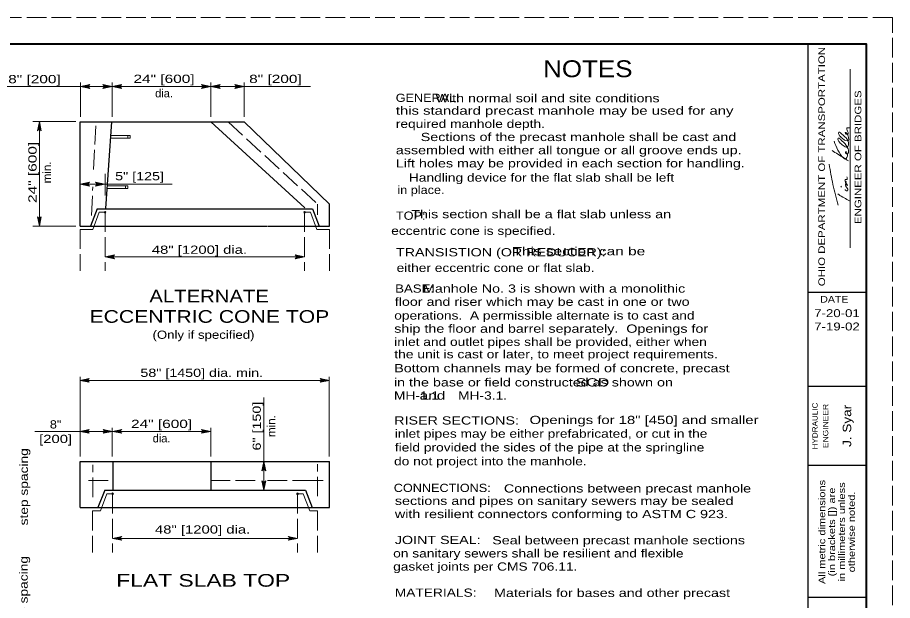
# Model space of a CAD drawing. Extents: x 808.4 to 842.4, y 1034.6 to 1056.6.
# Drawn here: x 825.84 to 842.44, y 1045.57 to 1056.63 of the extents above; entities that cross this region are included whole.
import ezdxf
from ezdxf.enums import TextEntityAlignment as Align

# ---------------------------------------------------------------- set-up
doc = ezdxf.new("R2010")
doc.units = 0
doc.header["$LTSCALE"] = 0.062
doc.header["$PDMODE"] = 32
doc.header["$PDSIZE"] = 0.031
doc.linetypes.add('LONG_DASHED', pattern=[7.5, 6, -1.5])
doc.layers.add('1', color=7, linetype='Continuous', lineweight=13)
doc.layers.add('10', color=7, linetype='Continuous')

msp = doc.modelspace()

# ---------------------------------------------------------------- linework, layer by layer
at = {"layer": '1', "lineweight": 25}
for p, q in [((840.83883, 1035.12767), (840.83883, 1056.12767)), ((827.02858, 1052.67158), (827.02858, 1054.6505)), ((827.02858, 1054.6505), (830.14142, 1054.6505)), ((827.51825, 1053.00408), (827.63133, 1054.64783)), ((831.29008, 1053.015), (829.51208, 1054.6505)), ((831.76025, 1053.08867), (830.14142, 1054.6505)), ((827.02858, 1052.67158), (827.02858, 1053.36142)), ((831.76025, 1052.67158), (831.76025, 1053.08867)), ((827.35492, 1053.00033), (827.22658, 1052.67158)), ((827.35492, 1053.00033), (827.22658, 1052.67158)), ((827.35492, 1053.00033), (831.27842, 1053.00033)), ((831.27842, 1053.00033), (831.43783, 1053.00033)), ((831.43783, 1053.00033), (831.56625, 1052.67158)), ((827.02858, 1052.67158), (830.57067, 1052.67158)), ((830.58167, 1052.67158), (831.27842, 1052.67158)), ((831.27842, 1052.67158), (831.76025, 1052.67158)), ((841.93883, 1051.41183), (840.83883, 1051.41183)), ((841.93883, 1049.62767), (840.83883, 1049.62767)), ((827.02858, 1048.20558), (831.27842, 1048.20558)), ((827.65292, 1048.20375), (827.65292, 1048.021)), ((829.51225, 1048.19792), (829.51225, 1048.021)), ((831.27842, 1048.20558), (831.76025, 1048.20558)), ((841.93883, 1048.12767), (840.83883, 1048.12767)), ((827.65292, 1048.021), (827.65292, 1047.66925)), ((829.51225, 1048.021), (829.51225, 1047.66342)), ((827.49775, 1047.66), (827.36933, 1047.33125)), ((827.49775, 1047.66), (827.36933, 1047.33125)), ((827.49775, 1047.66), (831.30233, 1047.66)), ((831.30233, 1047.66), (831.43075, 1047.33125)), ((831.30233, 1047.66), (831.43075, 1047.33125)), ((827.02858, 1047.33125), (830.58167, 1047.33125)), ((830.58167, 1047.33125), (831.76025, 1047.33125)), ((841.93883, 1045.62767), (840.83883, 1045.62767))]:
    msp.add_line(p, q, dxfattribs=at)
at = {"layer": '1'}
for p, q in [((841.63758, 1052.25867), (841.63758, 1055.64875)), ((827.19817, 1055.341), (827.03792, 1055.31858)), ((827.19275, 1055.32992), (827.03792, 1055.31858)), ((827.03958, 1055.39758), (827.03958, 1054.7455)), ((827.48025, 1055.341), (827.6405, 1055.31858)), ((827.48567, 1055.32992), (827.6405, 1055.31858)), ((827.64083, 1055.39758), (827.64083, 1054.7455)), ((827.80158, 1055.341), (827.64133, 1055.31858)), ((827.79617, 1055.32992), (827.64133, 1055.31858)), ((829.34942, 1055.341), (829.50967, 1055.31858)), ((829.35483, 1055.32992), (829.50967, 1055.31858)), ((829.51008, 1055.39758), (829.51008, 1054.7455)), ((829.67058, 1055.341), (829.51033, 1055.31858)), ((829.66517, 1055.32992), (829.51033, 1055.31858)), ((829.98075, 1055.341), (830.141, 1055.31858)), ((829.98617, 1055.32992), (830.141, 1055.31858)), ((830.13983, 1055.39758), (830.13983, 1054.7455)), ((827.19108, 1055.31858), (827.03792, 1055.31858)), ((827.19392, 1055.30417), (827.03792, 1055.31858)), ((827.20008, 1055.29383), (827.03792, 1055.31858)), ((827.47833, 1055.29383), (827.6405, 1055.31858)), ((827.4845, 1055.30417), (827.6405, 1055.31858)), ((827.48733, 1055.31858), (827.6405, 1055.31858)), ((827.7945, 1055.31858), (827.64133, 1055.31858)), ((827.79733, 1055.30417), (827.64133, 1055.31858)), ((827.80342, 1055.29383), (827.64133, 1055.31858)), ((829.3475, 1055.29383), (829.50967, 1055.31858)), ((829.35367, 1055.30417), (829.50967, 1055.31858)), ((829.3565, 1055.31858), (829.50967, 1055.31858)), ((829.6635, 1055.31858), (829.51033, 1055.31858)), ((829.66633, 1055.30417), (829.51033, 1055.31858)), ((829.6725, 1055.29383), (829.51033, 1055.31858)), ((829.97883, 1055.29383), (830.141, 1055.31858)), ((829.985, 1055.30417), (830.141, 1055.31858)), ((829.98783, 1055.31858), (830.141, 1055.31858)), ((826.13525, 1054.6555), (826.95033, 1054.6555)), ((826.23375, 1054.49333), (826.2585, 1054.6555)), ((826.24408, 1054.4995), (826.2585, 1054.6555)), ((826.2585, 1054.6555), (826.2585, 1052.67217)), ((826.2585, 1054.50233), (826.2585, 1054.6555)), ((826.26983, 1054.50067), (826.2585, 1054.6555)), ((826.28092, 1054.49525), (826.2585, 1054.6555)), ((827.60108, 1054.38967), (827.97917, 1054.38967)), ((827.60108, 1054.33667), (827.97917, 1054.33667)), ((827.93508, 1054.33733), (827.93508, 1054.39025)), ((827.97917, 1054.33667), (827.97917, 1054.38967)), ((827.02858, 1053.36142), (827.02858, 1053.54592)), ((827.50725, 1053.66275), (827.50725, 1053.25417)), ((827.19033, 1053.48925), (827.03008, 1053.46683)), ((827.18492, 1053.47817), (827.03008, 1053.46683)), ((827.03008, 1053.46683), (828.7735, 1053.46683)), ((827.18325, 1053.46683), (827.03008, 1053.46683)), ((827.18608, 1053.45242), (827.03008, 1053.46683)), ((827.19217, 1053.442), (827.03008, 1053.46683)), ((827.33808, 1053.442), (827.50025, 1053.46683)), ((827.34, 1053.48925), (827.50025, 1053.46683)), ((827.34425, 1053.45242), (827.50025, 1053.46683)), ((827.34542, 1053.47817), (827.50025, 1053.46683)), ((827.34708, 1053.46683), (827.50025, 1053.46683)), ((827.55483, 1053.43592), (827.93292, 1053.43592)), ((827.55483, 1053.38292), (827.93292, 1053.38292)), ((827.8895, 1053.383), (827.8895, 1053.436)), ((827.93292, 1053.38292), (827.93292, 1053.43592)), ((841.47008, 1053.40958), (841.45992, 1053.42883)), ((826.23608, 1052.83242), (826.2585, 1052.67217)), ((826.24717, 1052.827), (826.2585, 1052.67217)), ((826.28325, 1052.83433), (826.2585, 1052.67217)), ((826.27292, 1052.82817), (826.2585, 1052.67217)), ((826.2585, 1052.82533), (826.2585, 1052.67217)), ((826.13525, 1052.67217), (826.95033, 1052.67217)), ((827.66408, 1052.11092), (827.50383, 1052.0885)), ((827.65867, 1052.09983), (827.50383, 1052.0885)), ((827.50383, 1052.0885), (829.89875, 1052.0885)), ((827.657, 1052.0885), (827.50383, 1052.0885)), ((827.65983, 1052.07417), (827.50383, 1052.0885)), ((827.666, 1052.06375), (827.50383, 1052.0885)), ((829.89875, 1052.0885), (831.28892, 1052.0885)), ((831.12675, 1052.06375), (831.28892, 1052.0885)), ((831.12867, 1052.11092), (831.28892, 1052.0885)), ((831.13292, 1052.07417), (831.28892, 1052.0885)), ((831.13408, 1052.09983), (831.28892, 1052.0885)), ((831.13575, 1052.0885), (831.28892, 1052.0885)), ((827.18758, 1049.76725), (827.02733, 1049.74483)), ((827.18217, 1049.75608), (827.02733, 1049.74483)), ((827.1805, 1049.74483), (827.02733, 1049.74483)), ((827.18333, 1049.73042), (827.02733, 1049.74483)), ((827.18942, 1049.72), (827.02733, 1049.74483)), ((827.02883, 1049.80933), (827.02883, 1048.30242)), ((831.27842, 1049.74483), (831.7575, 1049.74483)), ((831.59533, 1049.72), (831.7575, 1049.74483)), ((831.59725, 1049.76725), (831.7575, 1049.74483)), ((831.6015, 1049.73042), (831.7575, 1049.74483)), ((831.60267, 1049.75608), (831.7575, 1049.74483)), ((831.60433, 1049.74483), (831.7575, 1049.74483)), ((831.75583, 1049.80933), (831.75583, 1048.30242)), ((830.51525, 1047.66), (830.51525, 1049.41808)), ((826.17175, 1048.77742), (829.13883, 1048.77742)), ((827.18758, 1048.79983), (827.02733, 1048.77742)), ((827.18217, 1048.78875), (827.02733, 1048.77742)), ((827.1805, 1048.77742), (827.02733, 1048.77742)), ((827.18333, 1048.763), (827.02733, 1048.77742)), ((827.1895, 1048.75267), (827.02733, 1048.77742)), ((827.47967, 1048.75267), (827.64175, 1048.77742)), ((827.4815, 1048.79983), (827.64175, 1048.77742)), ((827.48575, 1048.763), (827.64175, 1048.77742)), ((827.487, 1048.78875), (827.64175, 1048.77742)), ((827.48858, 1048.77742), (827.64175, 1048.77742)), ((827.64083, 1048.84383), (827.64083, 1048.30242)), ((827.802, 1048.79983), (827.64175, 1048.77742)), ((827.79658, 1048.78875), (827.64175, 1048.77742)), ((827.79492, 1048.77742), (827.64175, 1048.77742)), ((827.79775, 1048.763), (827.64175, 1048.77742)), ((827.80392, 1048.75267), (827.64175, 1048.77742)), ((829.13883, 1048.77742), (829.51008, 1048.77742)), ((829.345, 1048.75267), (829.50708, 1048.77742)), ((829.34683, 1048.79983), (829.50708, 1048.77742)), ((829.35108, 1048.763), (829.50708, 1048.77742)), ((829.35233, 1048.78875), (829.50708, 1048.77742)), ((829.35392, 1048.77742), (829.50708, 1048.77742)), ((829.51008, 1048.84383), (829.51008, 1048.30242)), ((830.49042, 1048.04617), (830.51525, 1048.20825)), ((830.50083, 1048.05225), (830.51525, 1048.20825)), ((830.51525, 1048.05508), (830.51525, 1048.20825)), ((830.52658, 1048.05342), (830.51525, 1048.20825)), ((830.53767, 1048.048), (830.51525, 1048.20825)), ((830.49283, 1047.82025), (830.51525, 1047.66)), ((830.50392, 1047.81483), (830.51525, 1047.66)), ((830.54, 1047.82217), (830.51525, 1047.66)), ((830.52967, 1047.816), (830.51525, 1047.66)), ((830.51525, 1047.81317), (830.51525, 1047.66)), ((827.80633, 1046.77058), (827.64608, 1046.74817)), ((827.80092, 1046.7595), (827.64608, 1046.74817)), ((827.64608, 1046.74817), (830.19917, 1046.74817)), ((827.79925, 1046.74817), (827.64608, 1046.74817)), ((827.80208, 1046.73383), (827.64608, 1046.74817)), ((827.80825, 1046.72342), (827.64608, 1046.74817)), ((830.19917, 1046.74817), (831.132, 1046.74817)), ((830.99183, 1046.72342), (831.154, 1046.74817)), ((830.99375, 1046.77058), (831.154, 1046.74817)), ((830.998, 1046.73383), (831.154, 1046.74817)), ((830.99917, 1046.7595), (831.154, 1046.74817)), ((831.00083, 1046.74817), (831.154, 1046.74817))]:
    msp.add_line(p, q, dxfattribs=at)
at = {"layer": '1', "linetype": 'LONG_DASHED'}
for p, q in [((827.2875, 1053.74525), (827.32842, 1054.57242)), ((829.83717, 1054.64767), (831.53192, 1053.08867)), ((827.24433, 1052.87308), (827.27117, 1053.41533)), ((831.53192, 1052.88592), (831.53192, 1053.08867)), ((827.3945, 1052.93358), (827.27158, 1052.60875)), ((831.39825, 1052.93358), (831.28892, 1052.93358)), ((831.28892, 1052.93358), (831.28892, 1051.8215)), ((831.39825, 1052.93358), (831.52125, 1052.60875)), ((827.19217, 1047.84242), (827.6515, 1047.84242)), ((829.50542, 1047.84242), (830.39125, 1047.84242)), ((830.5865, 1047.84242), (831.27842, 1047.84242)), ((831.27842, 1047.84242), (831.63808, 1047.84242)), ((827.53733, 1047.59325), (827.41433, 1047.26842)), ((831.26283, 1047.59325), (831.38575, 1047.26842)), ((827.26692, 1047.26892), (827.26692, 1046.48117)), ((827.41433, 1047.26892), (827.26692, 1047.26892)), ((831.38575, 1047.26892), (831.53317, 1047.26892)), ((831.53317, 1047.26892), (831.53317, 1046.48117))]:
    msp.add_line(p, q, dxfattribs=at)
msp.add_lwpolyline([(808.43883, 1034.62767), (842.43883, 1034.62767), (842.43883, 1056.62767), (808.43883, 1056.62767)], close=True, dxfattribs=at)
at = {"layer": '1', "lineweight": 25}
msp.add_lwpolyline([(810.43883, 1056.12767), (841.93883, 1056.12767), (841.93883, 1035.12767), (810.43883, 1035.12767)], close=True, dxfattribs=at)
at = {"layer": '1', "lineweight": 40}
msp.add_lwpolyline([(810.43883, 1056.12767), (841.93883, 1056.12767), (841.93883, 1035.12767), (810.43883, 1035.12767)], close=True, dxfattribs=at)
at = {"layer": '1'}
for points in [[(827.21492, 1055.28317), (827.03792, 1055.31858), (827.21492, 1055.354)], [(827.4635, 1055.28317), (827.6405, 1055.31858), (827.4635, 1055.354)], [(827.81833, 1055.28317), (827.64133, 1055.31858), (827.81833, 1055.354)], [(829.33267, 1055.28317), (829.50967, 1055.31858), (829.33267, 1055.354)], [(829.68733, 1055.28317), (829.51033, 1055.31858), (829.68733, 1055.354)], [(829.964, 1055.28317), (830.141, 1055.31858), (829.964, 1055.354)], [(825.64475, 1055.31858), (829.13883, 1055.31858), (831.39858, 1055.31858)], [(826.22308, 1054.4785), (826.2585, 1054.6555), (826.29392, 1054.4785)], [(827.20708, 1053.43142), (827.03008, 1053.46683), (827.20708, 1053.50225)], [(827.32325, 1053.43142), (827.50025, 1053.46683), (827.32325, 1053.50225)], [(826.29392, 1052.84917), (826.2585, 1052.67217), (826.22308, 1052.84917)], [(827.68083, 1052.05317), (827.50383, 1052.0885), (827.68083, 1052.12392)], [(831.11192, 1052.05317), (831.28892, 1052.0885), (831.11192, 1052.12392)], [(827.20433, 1049.70942), (827.02733, 1049.74483), (827.20433, 1049.78017)], [(827.02733, 1049.74483), (830.51042, 1049.74483), (831.27842, 1049.74483)], [(831.5805, 1049.70942), (831.7575, 1049.74483), (831.5805, 1049.78017)], [(827.20433, 1048.742), (827.02733, 1048.77742), (827.20433, 1048.81283)], [(827.46475, 1048.742), (827.64175, 1048.77742), (827.46475, 1048.81283)], [(827.81875, 1048.742), (827.64175, 1048.77742), (827.81875, 1048.81283)], [(829.33008, 1048.742), (829.50708, 1048.77742), (829.33008, 1048.81283)], [(830.47983, 1048.03125), (830.51525, 1048.20825), (830.55067, 1048.03125)], [(830.55067, 1047.837), (830.51525, 1047.66), (830.47983, 1047.837)], [(827.82308, 1046.71275), (827.64608, 1046.74817), (827.82308, 1046.78358)], [(830.977, 1046.71275), (831.154, 1046.74817), (830.977, 1046.78358)]]:
    msp.add_lwpolyline(points, dxfattribs=at)
at = {"layer": '1', "linetype": 'LONG_DASHED'}
for points in [[(827.3945, 1052.93358), (827.50383, 1052.93358), (827.50383, 1051.8215)], [(827.27158, 1052.60925), (827.03358, 1052.60925), (827.03358, 1051.8215)], [(831.52125, 1052.60925), (831.75917, 1052.60925), (831.75917, 1051.8215)], [(827.26875, 1047.52958), (827.26875, 1048.021), (827.26875, 1048.14017)], [(831.53192, 1047.54558), (831.53192, 1048.021), (831.53192, 1048.15617)], [(827.53733, 1047.59325), (827.64667, 1047.59325), (827.64667, 1046.48117)], [(831.26283, 1047.59325), (831.15342, 1047.59325), (831.15342, 1046.48117)]]:
    msp.add_lwpolyline(points, dxfattribs=at)
at = {"layer": '1', "lineweight": 25}
for points in [[(827.02858, 1047.33125), (827.02858, 1048.021), (827.02858, 1048.20558)], [(831.76025, 1047.33125), (831.76025, 1048.021), (831.76025, 1048.20558)]]:
    msp.add_lwpolyline(points, dxfattribs=at)
at = {"layer": '1'}
for centre, start, end in [((827.22923, 1055.31864), 112.08782, 247.91395), ((827.44918, 1055.31864), 292.08605, 67.91218), ((827.83261, 1055.31864), 112.08782, 247.91395), ((829.31836, 1055.31864), 292.08605, 67.91218), ((829.70165, 1055.31864), 112.08782, 247.91395), ((829.94971, 1055.31864), 292.08605, 67.91218), ((826.25854, 1054.46417), 22.08782, 157.91395), ((827.22136, 1053.46686), 112.08782, 247.91395), ((827.30896, 1053.46686), 292.08605, 67.91218), ((826.25846, 1052.86349), 202.08782, 337.91395), ((827.69517, 1052.08857), 112.08782, 247.91395), ((831.09763, 1052.08857), 292.08605, 67.91218), ((827.21861, 1049.74483), 112.08782, 247.91395), ((831.56616, 1049.74483), 292.08605, 67.91218), ((827.21864, 1048.77747), 112.08782, 247.91395), ((827.45048, 1048.77747), 292.08605, 67.91218), ((827.83307, 1048.77747), 112.08782, 247.91395), ((829.31581, 1048.77747), 292.08605, 67.91218), ((830.51527, 1048.01697), 22.08782, 157.91395), ((830.51519, 1047.85129), 202.08782, 337.91395), ((827.8374, 1046.74823), 112.08782, 247.91395), ((830.96271, 1046.74823), 292.08605, 67.91218)]:
    msp.add_arc(centre, 0.0382, start, end, dxfattribs=at)
for points in [[(841.33067, 1054.28467), (841.51383, 1053.95633), (841.529, 1053.94575), (841.53917, 1053.94575), (841.57108, 1053.96942), (841.58617, 1054.00358), (841.58117, 1054.05483), (841.56425, 1054.07667), (841.55075, 1054.07667), (841.549, 1054.06367), (841.55917, 1054.0485), (841.57267, 1054.04008), (841.58775, 1054.04008), (841.60292, 1054.06167), (841.60633, 1054.081), (841.59608, 1054.13633), (841.51383, 1054.25675), (841.46833, 1054.30142), (841.43142, 1054.336), (841.40625, 1054.33817), (841.408, 1054.29958), (841.43317, 1054.26083), (841.50042, 1054.1985), (841.5425, 1054.17308), (841.57617, 1054.16858), (841.5995, 1054.19458), (841.60633, 1054.22875), (841.60125, 1054.2545), (841.57108, 1054.32767), (841.54083, 1054.35967), (841.48025, 1054.41308), (841.45158, 1054.43892), (841.41808, 1054.45417), (841.41467, 1054.42617), (841.42475, 1054.40033), (841.48192, 1054.34042), (841.55258, 1054.29317), (841.60458, 1054.2955), (841.60292, 1054.35317), (841.59108, 1054.39608), (841.57775, 1054.42183), (841.56758, 1054.43258), (841.54417, 1054.44758), (841.54592, 1054.4305), (841.58117, 1054.409), (841.59608, 1054.41975), (841.583, 1054.47342), (841.57442, 1054.50133), (841.57108, 1054.514), (841.57108, 1054.52683), (841.57108, 1054.5355), (841.59608, 1054.53333), (841.6215, 1054.53333)], [(841.29183, 1054.10242), (841.51558, 1053.96492), (841.60125, 1053.90925)], [(841.40808, 1053.06542), (841.30942, 1053.46067), (841.23817, 1053.843)], [(841.53917, 1053.36433), (841.54742, 1053.35367), (841.58458, 1053.34075), (841.58933, 1053.37317), (841.56425, 1053.40958), (841.549, 1053.44583), (841.549, 1053.46508), (841.56425, 1053.45883), (841.57442, 1053.448), (841.58458, 1053.44367), (841.56092, 1053.47583), (841.549, 1053.49083), (841.54592, 1053.50817), (841.56933, 1053.50158), (841.56092, 1053.51025), (841.53575, 1053.53808), (841.54592, 1053.55325), (841.56267, 1053.55525), (841.57108, 1053.55325), (841.58117, 1053.57458), (841.57442, 1053.6025)], [(841.62325, 1053.14983), (841.41808, 1053.26983), (841.4025, 1053.28025)]]:
    msp.add_spline(points, degree=3, dxfattribs=at)
for p in [(827.50383, 1052.93358), (831.28892, 1052.93358), (827.64667, 1047.59325), (831.15342, 1047.59325)]:
    msp.add_point(p, dxfattribs=at)

# ---------------------------------------------------------------- texts
for s, height, width, p in [('OHIO DEPARTMENT OF TRANSPORTATION', 0.125, 1.3, (841.15875, 1053.79992)), ('ENGINEER OF BRIDGES', 0.125, 1.3, (841.84708, 1053.97671)), ('HYDRAULIC', 0.1, 1.15, (841.01792, 1048.87875)), ('ENGINEER', 0.1, 1.2, (841.21883, 1048.87879)), ('J. Syar', 0.16, 1.2, (841.65525, 1048.88179)), ('All metric dimensions', 0.125, 1.25, (841.16267, 1046.86975)), ('(in brackets []) are', 0.125, 1.25, (841.35017, 1046.86975)), ('in millimeters unless', 0.125, 1.25, (841.53767, 1046.86979)), ('otherwise noted.', 0.125, 1.25, (841.72517, 1046.86975))]:
    msp.add_text(s, height=height, rotation=90, dxfattribs=dict(at, width=width)).set_placement(p, align=Align.CENTER)
for s, height, width, p in [('DATE', 0.125, 1.2, (841.33554, 1051.22042)), ('7-20-01', 0.15, 1.25, (841.38587, 1050.94492)), ('7-19-02', 0.15, 1.25, (841.38587, 1050.69183))]:
    msp.add_text(s, height=height, dxfattribs=dict(at, width=width)).set_placement(p, align=Align.CENTER)
at = {"layer": '10'}
for s, height, width, p in [('NOTES', 0.32, 1.15, (836.66029, 1055.49558)), ('24" [600]', 0.156, 1.4, (828.62229, 1055.38683)), ('8"', 0.156, 1.15, (826.56608, 1048.83208)), ('24" [600]', 0.156, 1.4, (828.57579, 1048.84183)), ('[200]', 0.156, 1.35, (826.56608, 1048.55608))]:
    msp.add_text(s, height=height, dxfattribs=dict(at, width=width)).set_placement(p, align=Align.CENTER)
for s, height, width, p in [('8" [200]', 0.156, 1.4, (825.66608, 1055.38092)), ('8" [200]', 0.156, 1.4, (830.23675, 1055.385)), ('GENERAL:', 0.156, 1.15, (833.01667, 1055.02625)), ('          With normal soil and site conditions ', 0.156, 1.3, (833.01717, 1055.01867)), ('this standard precast manhole may be used for any ', 0.156, 1.35, (833.019, 1054.78333)), ('required manhole depth.', 0.156, 1.25, (833.019, 1054.53342)), ('Sections of the precast manhole shall be cast and', 0.156, 1.3, (833.491, 1054.28358)), ('assembled with either all tongue or all groove ends up.', 0.156, 1.3, (833.019, 1054.03375)), ('Lift holes may be provided in each section for handling.', 0.156, 1.3, (833.019, 1053.78392)), ('5" [125]', 0.156, 1.3, (827.69542, 1053.54033)), ('   Handling device for the flat slab shall be left', 0.156, 1.25, (833.04883, 1053.51358)), ('in place.', 0.156, 1.15, (833.04883, 1053.27958)), ('TOP:', 0.156, 1.15, (833.02117, 1052.791)), ('      This section shall be a flat slab unless an', 0.156, 1.3, (832.85833, 1052.82025)), (' eccentric cone is specified.', 0.156, 1.25, (832.85833, 1052.50425)), ('48" [1200] dia. ', 0.156, 1.35, (828.39058, 1052.14525)), ('TRANSISTION (OR REDUCER):', 0.156, 1.3, (833.02117, 1052.09658)), ('                            This section can be', 0.156, 1.4, (832.96067, 1052.1175)), (' either eccentric cone or flat slab.', 0.156, 1.25, (832.96067, 1051.8015)), ('BASE:', 0.156, 1.2, (833.00625, 1051.40825)), ('       Manhole No. 3 is shown with a monolithic', 0.156, 1.3, (833.00625, 1051.40825)), ('ALTERNATE', 0.24, 1.2, (828.34417, 1051.22275)), ('floor and riser which may be cast in one or two', 0.156, 1.3, (832.99817, 1051.15833)), ('ECCENTRIC CONE TOP', 0.24, 1.25, (827.20925, 1050.83667)), ('operations.  A permissible alternate is to cast and', 0.156, 1.25, (832.98833, 1050.89758)), ('(Only if specified)', 0.156, 1.2, (828.40375, 1050.53267)), ('ship the floor and barrel separately.  Openings for', 0.156, 1.3, (832.98833, 1050.64775)), ('inlet and outlet pipes shall be provided, either when', 0.156, 1.25, (832.98833, 1050.39792)), ('the unit is cast or later, to meet project requirements.', 0.1573, 1.25, (832.98833, 1050.16308)), ('Bottom channels may be formed of concrete, precast', 0.156, 1.3, (832.98833, 1049.89817)), ('58" [1450] dia. min.', 0.156, 1.3, (828.1735, 1049.81042)), ('in the base or field constructed as shown on', 0.156, 1.3, (832.98308, 1049.629)), ('                                         SCD', 0.156, 1.45, (832.98308, 1049.629)), ('MH-1.1     MH-3.1.', 0.156, 1.25, (832.98308, 1049.37917)), ('      and', 0.156, 1.4, (832.98308, 1049.37917)), ('RISER SECTIONS:', 0.156, 1.3, (832.98792, 1048.9065)), ('Openings for 18" [450] and smaller', 0.156, 1.35, (835.55508, 1048.91617)), ('inlet pipes may be either prefabricated, or cut in the', 0.156, 1.25, (832.9995, 1048.65667)), ('field provided the sides of the pipe at the springline', 0.156, 1.25, (832.99942, 1048.39567)), ('do not project into the manhole.', 0.156, 1.25, (832.98533, 1048.13408)), ('CONNECTIONS:', 0.156, 1.15, (832.97992, 1047.62758)), ('Connections between precast manhole', 0.156, 1.3, (835.06817, 1047.61767)), ('sections and pipes on sanitary sewers may be sealed', 0.156, 1.3, (833.00092, 1047.38158)), ('with resilient connectors conforming to ASTM C 923.', 0.156, 1.3, (833.00092, 1047.13167)), ('48" [1200] dia. ', 0.156, 1.35, (828.45042, 1046.839)), ('JOINT SEAL:', 0.156, 1.3, (832.999, 1046.63975)), ('Seal between precast manhole sections', 0.156, 1.3, (834.84683, 1046.63425)), ('on sanitary sewers shall be resilient and flexible', 0.156, 1.25, (832.96792, 1046.38525)), ('gasket joints per CMS 706.11.', 0.156, 1.25, (832.96792, 1046.13542)), ('FLAT SLAB TOP', 0.24, 1.35, (827.71583, 1045.83142)), ('MATERIALS:', 0.156, 1.25, (832.999, 1045.64033)), ('Materials for bases and other precast', 0.156, 1.3, (834.88125, 1045.63558))]:
    msp.add_text(s, height=height, dxfattribs=dict(at, width=width)).set_placement(p)
for p in [(828.62229, 1055.11283), (828.57579, 1048.56783)]:
    msp.add_text('dia.', height=0.156, dxfattribs=at).set_placement(p, align=Align.CENTER)
for s, width, p in [('24" [600]', 1.4, (826.20517, 1053.68954)), ('min.', 1.05, (826.47917, 1053.6895)), ('6" [150]', 1.3, (830.4585, 1048.87758)), ('min.', 1.05, (830.7325, 1048.87758)), ('step spacing', 1.25, (826.0405, 1047.72604)), ('step spacing', 1.25, (826.03675, 1045.68096))]:
    msp.add_text(s, height=0.156, rotation=90, dxfattribs=dict(at, width=width)).set_placement(p, align=Align.CENTER)

doc.saveas('drawing.dxf')
